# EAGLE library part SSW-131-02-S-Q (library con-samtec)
THROUGH-HOLE .025" SQ POST SOCKET Source: Samtec SSW.pdf
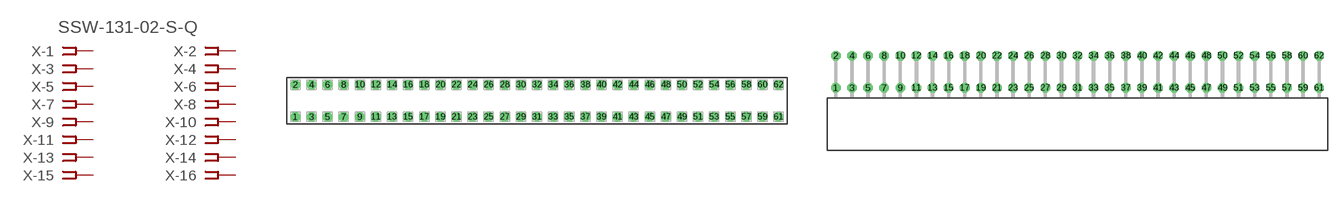
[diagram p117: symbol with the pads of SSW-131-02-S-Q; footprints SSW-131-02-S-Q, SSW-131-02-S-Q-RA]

Designator prefix X; gates -1=FPINV -2=FPIN -3=FPIN -4=FPIN -5=FPIN -6=FPIN -7=FPIN -8=FPIN -9=FPIN -10=FPIN -11=FPIN -12=FPIN -13=FPIN -14=FPIN -15=FPIN -16=FPIN -17=FPIN -18=FPIN -19=FPIN -20=FPIN -21=FPIN -22=FPIN -23=FPIN -24=FPIN -25=FPIN -26=FPIN -27=FPIN -28=FPIN -29=FPIN -30=FPIN -31=FPIN -32=FPIN -33=FPIN -34=FPIN -35=FPIN -36=FPIN -37=FPIN -38=FPIN -39=FPIN -40=FPIN -41=FPIN -42=FPIN -43=FPIN -44=FPIN -45=FPIN -46=FPIN -47=FPIN -48=FPIN -49=FPIN -50=FPIN -51=FPIN -52=FPIN -53=FPIN -54=FPIN -55=FPIN -56=FPIN -57=FPIN -58=FPIN -59=FPIN -60=FPIN -61=FPIN -62=FPIN

## SSW-131-02-S-Q (MPN: SSW-131-02-S-Q; OC_FARNELL: unknown; OC_NEWARK: 83P0231)  [SSW-131-02-S-Q]
1  -1:1  pas
2  -2:1  pas
3  -3:1  pas
4  -4:1  pas
5  -5:1  pas
6  -6:1  pas
7  -7:1  pas
8  -8:1  pas
9  -9:1  pas
10  -10:1  pas
11  -11:1  pas
12  -12:1  pas
13  -13:1  pas
14  -14:1  pas
15  -15:1  pas
16  -16:1  pas
17  -17:1  pas
18  -18:1  pas
19  -19:1  pas
20  -20:1  pas
21  -21:1  pas
22  -22:1  pas
23  -23:1  pas
24  -24:1  pas
25  -25:1  pas
26  -26:1  pas
27  -27:1  pas
28  -28:1  pas
29  -29:1  pas
30  -30:1  pas
31  -31:1  pas
32  -32:1  pas
33  -33:1  pas
34  -34:1  pas
35  -35:1  pas
36  -36:1  pas
37  -37:1  pas
38  -38:1  pas
39  -39:1  pas
40  -40:1  pas
41  -41:1  pas
42  -42:1  pas
43  -43:1  pas
44  -44:1  pas
45  -45:1  pas
46  -46:1  pas
47  -47:1  pas
48  -48:1  pas
49  -49:1  pas
50  -50:1  pas
51  -51:1  pas
52  -52:1  pas
53  -53:1  pas
54  -54:1  pas
55  -55:1  pas
56  -56:1  pas
57  -57:1  pas
58  -58:1  pas
59  -59:1  pas
60  -60:1  pas
61  -61:1  pas
62  -62:1  pas

## SSW-131-02-S-QRA (OC_FARNELL: unknown; OC_NEWARK: unknown)  [SSW-131-02-S-Q-RA]
Pads as for SSW-131-02-S-Q

## Footprint SSW-131-02-S-Q (pad centres in mm)
THROUGH-HOLE .025" SQ POST SOCKET Source: Samtec SSW.pdf
drill 1 pad 1.5 octagon: 1 -38.1,-2.54; 2 -38.1,2.54; 3 -35.56,-2.54; 4 -35.56,2.54; 5 -33.02,-2.54; 6 -33.02,2.54; 7 -30.48,-2.54; 8 -30.48,2.54; 9 -27.94,-2.54; 10 -27.94,2.54; 11 -25.4,-2.54; 12 -25.4,2.54; 13 -22.86,-2.54; 14 -22.86,2.54; 15 -20.32,-2.54; 16 -20.32,2.54; 17 -17.78,-2.54; 18 -17.78,2.54; 19 -15.24,-2.54; 20 -15.24,2.54; 21 -12.7,-2.54; 22 -12.7,2.54; 23 -10.16,-2.54; 24 -10.16,2.54; 25 -7.62,-2.54; 26 -7.62,2.54; 27 -5.08,-2.54; 28 -5.08,2.54; 29 -2.54,-2.54; 30 -2.54,2.54; 31 0,-2.54; 32 0,2.54; 33 2.54,-2.54; 34 2.54,2.54; 35 5.08,-2.54; 36 5.08,2.54; 37 7.62,-2.54; 38 7.62,2.54; 39 10.16,-2.54; 40 10.16,2.54; 41 12.7,-2.54; 42 12.7,2.54; 43 15.24,-2.54; 44 15.24,2.54; 45 17.78,-2.54; 46 17.78,2.54; 47 20.32,-2.54; 48 20.32,2.54; 49 22.86,-2.54; 50 22.86,2.54; 51 25.4,-2.54; 52 25.4,2.54; 53 27.94,-2.54; 54 27.94,2.54; 55 30.48,-2.54; 56 30.48,2.54; 57 33.02,-2.54; 58 33.02,2.54; 59 35.56,-2.54; 60 35.56,2.54; 61 38.1,-2.54; 62 38.1,2.54

## Footprint SSW-131-02-S-Q-RA (pad centres in mm)
THROUGH-HOLE .025" SQ POST SOCKET Source: Samtec SSW.pdf
drill 1 pad 1.5 octagon: 1 -38.1,1.524; 2 -38.1,6.604; 3 -35.56,1.524; 4 -35.56,6.604; 5 -33.02,1.524; 6 -33.02,6.604; 7 -30.48,1.524; 8 -30.48,6.604; 9 -27.94,1.524; 10 -27.94,6.604; 11 -25.4,1.524; 12 -25.4,6.604; 13 -22.86,1.524; 14 -22.86,6.604; 15 -20.32,1.524; 16 -20.32,6.604; 17 -17.78,1.524; 18 -17.78,6.604; 19 -15.24,1.524; 20 -15.24,6.604; 21 -12.7,1.524; 22 -12.7,6.604; 23 -10.16,1.524; 24 -10.16,6.604; 25 -7.62,1.524; 26 -7.62,6.604; 27 -5.08,1.524; 28 -5.08,6.604; 29 -2.54,1.524; 30 -2.54,6.604; 31 0,1.524; 32 0,6.604; 33 2.54,1.524; 34 2.54,6.604; 35 5.08,1.524; 36 5.08,6.604; 37 7.62,1.524; 38 7.62,6.604; 39 10.16,1.524; 40 10.16,6.604; 41 12.7,1.524; 42 12.7,6.604; 43 15.24,1.524; 44 15.24,6.604; 45 17.78,1.524; 46 17.78,6.604; 47 20.32,1.524; 48 20.32,6.604; 49 22.86,1.524; 50 22.86,6.604; 51 25.4,1.524; 52 25.4,6.604; 53 27.94,1.524; 54 27.94,6.604; 55 30.48,1.524; 56 30.48,6.604; 57 33.02,1.524; 58 33.02,6.604; 59 35.56,1.524; 60 35.56,6.604; 61 38.1,1.524; 62 38.1,6.604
